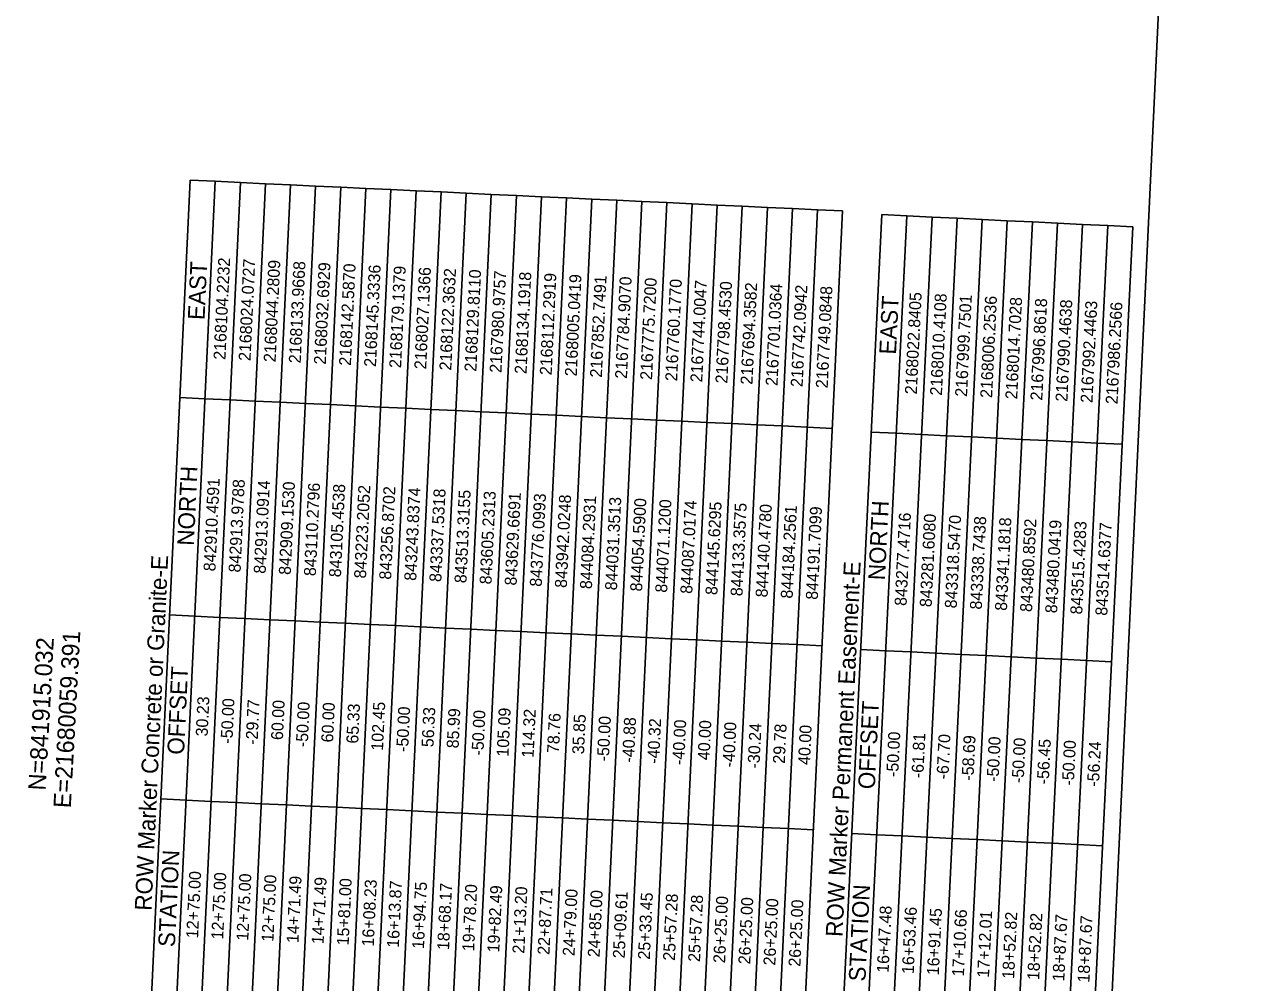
# Model space of a CAD drawing. Extents: x 2167298 to 2168977, y 841960 to 844561.
# Drawn here: x 2168145 to 2168977, y 842342 to 842987 of the extents above; entities that cross this region are included whole.
import ezdxf

# ---------------------------------------------------------------- set-up
doc = ezdxf.new("R2010")
doc.units = 0
for name, color, linetype in [('CTL GPS Vertical Text', 7, 'Continuous'), ('CTL Sheet Border CELL', 7, 'Continuous'), ('CTL Sheet Notes CELL', 7, 'Continuous'), ('CTL Sheet Table Cell', 7, 'Continuous'), ('CTL Sheet Text', 7, 'Continuous')]:
    doc.layers.add(name, color=color, linetype=linetype)

msp = doc.modelspace()

# ---------------------------------------------------------------- linework, layer by layer
at = {"layer": 'CTL Sheet Border CELL'}
msp.add_lwpolyline([(2167403.66, 844533.83), (2167297.51, 842286.33), (2168870.75, 842212.02), (2168976.9, 844459.52)], close=True, dxfattribs=at)
at = {"layer": 'CTL Sheet Table Cell'}
for p, q in [((2168226.19, 842251.66), (2168255.97, 842882.28)), ((2168255.97, 842882.28), (2168272.86, 842881.48)), ((2168243.08, 842250.86), (2168272.86, 842881.48)), ((2168259.97, 842250.06), (2168289.76, 842880.68)), ((2168272.86, 842881.48), (2168289.76, 842880.68)), ((2168276.86, 842249.27), (2168306.65, 842879.88)), ((2168289.76, 842880.68), (2168306.65, 842879.88)), ((2168293.75, 842248.47), (2168323.54, 842879.09)), ((2168306.65, 842879.88), (2168323.54, 842879.09)), ((2168310.65, 842247.67), (2168340.43, 842878.29)), ((2168323.54, 842879.09), (2168340.43, 842878.29)), ((2168327.54, 842246.87), (2168357.32, 842877.49)), ((2168340.43, 842878.29), (2168357.32, 842877.49)), ((2168344.43, 842246.08), (2168374.21, 842876.69)), ((2168357.32, 842877.49), (2168374.21, 842876.69)), ((2168361.32, 842245.28), (2168391.1, 842875.9)), ((2168374.21, 842876.69), (2168391.1, 842875.9)), ((2168378.21, 842244.48), (2168408, 842875.1)), ((2168391.1, 842875.9), (2168408, 842875.1)), ((2168395.1, 842243.68), (2168424.89, 842874.3)), ((2168408, 842875.1), (2168424.89, 842874.3)), ((2168424.89, 842874.3), (2168441.78, 842873.5)), ((2168411.99, 842242.88), (2168441.78, 842873.5)), ((2168428.89, 842242.09), (2168458.67, 842872.7)), ((2168441.78, 842873.5), (2168458.67, 842872.7)), ((2168445.78, 842241.29), (2168475.56, 842871.91)), ((2168458.67, 842872.7), (2168475.56, 842871.91)), ((2168462.67, 842240.49), (2168492.45, 842871.11)), ((2168475.56, 842871.91), (2168492.45, 842871.11)), ((2168479.56, 842239.69), (2168509.35, 842870.31)), ((2168492.45, 842871.11), (2168509.35, 842870.31)), ((2168496.45, 842238.9), (2168526.24, 842869.51)), ((2168509.35, 842870.31), (2168526.24, 842869.51)), ((2168513.34, 842238.1), (2168543.13, 842868.72)), ((2168526.24, 842869.51), (2168543.13, 842868.72)), ((2168530.24, 842237.3), (2168560.02, 842867.92)), ((2168543.13, 842868.72), (2168560.02, 842867.92)), ((2168547.13, 842236.5), (2168576.91, 842867.12)), ((2168560.02, 842867.92), (2168576.91, 842867.12)), ((2168564.02, 842235.7), (2168593.8, 842866.32)), ((2168576.91, 842867.12), (2168593.8, 842866.32)), ((2168593.8, 842866.32), (2168610.69, 842865.52)), ((2168580.91, 842234.91), (2168610.69, 842865.52)), ((2168597.8, 842234.11), (2168627.59, 842864.73)), ((2168610.69, 842865.52), (2168627.59, 842864.73)), ((2168614.69, 842233.31), (2168644.48, 842863.93)), ((2168627.59, 842864.73), (2168644.48, 842863.93)), ((2168631.58, 842232.51), (2168661.37, 842863.13)), ((2168644.48, 842863.93), (2168661.37, 842863.13)), ((2168648.48, 842231.72), (2168678.26, 842862.33)), ((2168661.37, 842863.13), (2168678.26, 842862.33)), ((2168665.37, 842230.92), (2168695.15, 842861.54)), ((2168678.26, 842862.33), (2168695.15, 842861.54)), ((2168690.79, 842228.46), (2168721.52, 842859.03)), ((2168707.68, 842227.63), (2168738.41, 842858.2)), ((2168721.52, 842859.03), (2168738.41, 842858.2)), ((2168724.57, 842226.81), (2168755.3, 842857.38)), ((2168738.41, 842858.2), (2168755.3, 842857.38)), ((2168755.3, 842857.38), (2168772.19, 842856.56)), ((2168741.46, 842225.99), (2168772.19, 842856.56)), ((2168758.35, 842225.16), (2168789.08, 842855.74)), ((2168772.19, 842856.56), (2168789.08, 842855.74)), ((2168775.24, 842224.34), (2168805.97, 842854.91)), ((2168789.08, 842855.74), (2168805.97, 842854.91)), ((2168792.13, 842223.52), (2168822.86, 842854.09)), ((2168805.97, 842854.91), (2168822.86, 842854.09)), ((2168809.02, 842222.69), (2168839.75, 842853.27)), ((2168822.86, 842854.09), (2168839.75, 842853.27)), ((2168825.91, 842221.87), (2168856.64, 842852.44)), ((2168839.75, 842853.27), (2168856.64, 842852.44)), ((2168842.8, 842221.05), (2168873.53, 842851.62)), ((2168856.64, 842852.44), (2168873.53, 842851.62)), ((2168859.69, 842220.22), (2168890.42, 842850.8)), ((2168873.53, 842851.62), (2168890.42, 842850.8)), ((2168249.06, 842735.88), (2168265.95, 842735.09)), ((2168265.95, 842735.09), (2168282.84, 842734.29)), ((2168282.84, 842734.29), (2168299.73, 842733.49)), ((2168299.73, 842733.49), (2168316.62, 842732.69)), ((2168316.62, 842732.69), (2168333.52, 842731.9)), ((2168333.52, 842731.9), (2168350.41, 842731.1)), ((2168350.41, 842731.1), (2168367.3, 842730.3)), ((2168367.3, 842730.3), (2168384.19, 842729.5)), ((2168384.19, 842729.5), (2168401.08, 842728.7)), ((2168401.08, 842728.7), (2168417.97, 842727.91)), ((2168417.97, 842727.91), (2168434.86, 842727.11)), ((2168434.86, 842727.11), (2168451.76, 842726.31)), ((2168451.76, 842726.31), (2168468.65, 842725.51)), ((2168468.65, 842725.51), (2168485.54, 842724.72)), ((2168485.54, 842724.72), (2168502.43, 842723.92)), ((2168502.43, 842723.92), (2168519.32, 842723.12)), ((2168519.32, 842723.12), (2168536.21, 842722.32)), ((2168536.21, 842722.32), (2168553.11, 842721.52)), ((2168553.11, 842721.52), (2168570, 842720.73)), ((2168570, 842720.73), (2168586.89, 842719.93)), ((2168586.89, 842719.93), (2168603.78, 842719.13)), ((2168603.78, 842719.13), (2168620.67, 842718.33)), ((2168620.67, 842718.33), (2168637.56, 842717.54)), ((2168637.56, 842717.54), (2168654.45, 842716.74)), ((2168654.45, 842716.74), (2168671.35, 842715.94)), ((2168671.35, 842715.94), (2168688.24, 842715.14)), ((2168714.39, 842712.65), (2168731.28, 842711.82)), ((2168731.28, 842711.82), (2168748.17, 842711)), ((2168748.17, 842711), (2168765.06, 842710.18)), ((2168765.06, 842710.18), (2168781.95, 842709.35)), ((2168781.95, 842709.35), (2168798.84, 842708.53)), ((2168798.84, 842708.53), (2168815.73, 842707.71)), ((2168815.73, 842707.71), (2168832.62, 842706.88)), ((2168832.62, 842706.88), (2168849.51, 842706.06)), ((2168849.51, 842706.06), (2168866.4, 842705.24)), ((2168866.4, 842705.24), (2168883.29, 842704.41)), ((2168242.14, 842589.49), (2168259.04, 842588.69)), ((2168259.04, 842588.69), (2168275.93, 842587.9)), ((2168275.93, 842587.9), (2168292.82, 842587.1)), ((2168292.82, 842587.1), (2168309.71, 842586.3)), ((2168309.71, 842586.3), (2168326.6, 842585.5)), ((2168326.6, 842585.5), (2168343.49, 842584.7)), ((2168343.49, 842584.7), (2168360.38, 842583.91)), ((2168360.38, 842583.91), (2168377.28, 842583.11)), ((2168377.28, 842583.11), (2168394.17, 842582.31)), ((2168394.17, 842582.31), (2168411.06, 842581.51)), ((2168411.06, 842581.51), (2168427.95, 842580.72)), ((2168427.95, 842580.72), (2168444.84, 842579.92)), ((2168444.84, 842579.92), (2168461.73, 842579.12)), ((2168461.73, 842579.12), (2168478.63, 842578.32)), ((2168478.63, 842578.32), (2168495.52, 842577.52)), ((2168495.52, 842577.52), (2168512.41, 842576.73)), ((2168512.41, 842576.73), (2168529.3, 842575.93)), ((2168529.3, 842575.93), (2168546.19, 842575.13)), ((2168546.19, 842575.13), (2168563.08, 842574.33)), ((2168563.08, 842574.33), (2168579.97, 842573.54)), ((2168579.97, 842573.54), (2168596.87, 842572.74)), ((2168596.87, 842572.74), (2168613.76, 842571.94)), ((2168613.76, 842571.94), (2168630.65, 842571.14)), ((2168630.65, 842571.14), (2168647.54, 842570.34)), ((2168647.54, 842570.34), (2168664.43, 842569.55)), ((2168664.43, 842569.55), (2168681.32, 842568.75)), ((2168707.25, 842566.26), (2168724.14, 842565.44)), ((2168724.14, 842565.44), (2168741.03, 842564.62)), ((2168741.03, 842564.62), (2168757.92, 842563.79)), ((2168757.92, 842563.79), (2168774.81, 842562.97)), ((2168774.81, 842562.97), (2168791.7, 842562.15)), ((2168791.7, 842562.15), (2168808.59, 842561.32)), ((2168808.59, 842561.32), (2168825.48, 842560.5)), ((2168825.48, 842560.5), (2168842.37, 842559.68)), ((2168842.37, 842559.68), (2168859.26, 842558.85)), ((2168859.26, 842558.85), (2168876.15, 842558.03)), ((2168236.29, 842465.62), (2168253.18, 842464.82)), ((2168253.18, 842464.82), (2168270.08, 842464.02)), ((2168270.08, 842464.02), (2168286.97, 842463.23)), ((2168286.97, 842463.23), (2168303.86, 842462.43)), ((2168303.86, 842462.43), (2168320.75, 842461.63)), ((2168320.75, 842461.63), (2168337.64, 842460.83)), ((2168337.64, 842460.83), (2168354.53, 842460.04)), ((2168354.53, 842460.04), (2168371.43, 842459.24)), ((2168371.43, 842459.24), (2168388.32, 842458.44)), ((2168388.32, 842458.44), (2168405.21, 842457.64)), ((2168405.21, 842457.64), (2168422.1, 842456.84)), ((2168422.1, 842456.84), (2168438.99, 842456.05)), ((2168438.99, 842456.05), (2168455.88, 842455.25)), ((2168455.88, 842455.25), (2168472.77, 842454.45)), ((2168472.77, 842454.45), (2168489.67, 842453.65)), ((2168489.67, 842453.65), (2168506.56, 842452.86)), ((2168506.56, 842452.86), (2168523.45, 842452.06)), ((2168523.45, 842452.06), (2168540.34, 842451.26)), ((2168540.34, 842451.26), (2168557.23, 842450.46)), ((2168557.23, 842450.46), (2168574.12, 842449.66)), ((2168574.12, 842449.66), (2168591.02, 842448.87)), ((2168591.02, 842448.87), (2168607.91, 842448.07)), ((2168607.91, 842448.07), (2168624.8, 842447.27)), ((2168624.8, 842447.27), (2168641.69, 842446.47)), ((2168641.69, 842446.47), (2168658.58, 842445.68)), ((2168658.58, 842445.68), (2168675.47, 842444.88)), ((2168701.21, 842442.4), (2168718.1, 842441.58)), ((2168718.1, 842441.58), (2168735, 842440.75)), ((2168735, 842440.75), (2168751.89, 842439.93)), ((2168751.89, 842439.93), (2168768.78, 842439.11)), ((2168768.78, 842439.11), (2168785.67, 842438.28)), ((2168785.67, 842438.28), (2168802.56, 842437.46)), ((2168802.56, 842437.46), (2168819.45, 842436.64)), ((2168819.45, 842436.64), (2168836.34, 842435.81)), ((2168836.34, 842435.81), (2168853.23, 842434.99)), ((2168853.23, 842434.99), (2168870.12, 842434.17))]:
    msp.add_line(p, q, dxfattribs=at)

# ---------------------------------------------------------------- texts
at = {"layer": 'CTL GPS Vertical Text'}
for s, p in [('E=21680059.391', (2168175.58, 842459.25)), ('N=841915.032', (2168158.67, 842471.14))]:
    msp.add_text(s, height=11.6923, rotation=86.87788, dxfattribs=at).set_placement(p)
at = {"layer": 'CTL Sheet Notes CELL'}
for s, height, rotation, p in [('EAST', 11.274, 87.29593, (2168265.62, 842787.93)), ('EAST', 11.274, 87.20981, (2168731.03, 842764.67)), ('NORTH', 11.274, 87.29593, (2168258.45, 842635.95)), ('NORTH', 11.274, 87.20981, (2168723.62, 842612.7)), ('ROW Marker Concrete or Granite-E', 11.2736, 87.29593, (2168229.91, 842390.21)), ('ROW Marker Permanent Easement-E', 11.2736, 87.20981, (2168694.99, 842372.58)), ('OFFSET', 11.274, 87.29593, (2168251.8, 842495.24)), ('OFFSET', 11.274, 87.20981, (2168716.77, 842471.99)), ('STATION', 11.274, 87.29593, (2168245.69, 842365.78)), ('STATION', 11.274, 87.20981, (2168710.46, 842342.54))]:
    msp.add_text(s, height=height, rotation=rotation, dxfattribs=at).set_placement(p)
at = {"layer": 'CTL Sheet Text'}
for s, height, rotation, p in [('2168104.2232', 8.0526, 87.29593, (2168279.68, 842761.14)), ('2168024.0727', 8.0526, 87.29593, (2168296.57, 842760.35)), ('2168044.2809', 8.0526, 87.29593, (2168313.46, 842759.55)), ('2168133.9668', 8.0526, 87.29593, (2168330.35, 842758.75)), ('2168032.6929', 8.0526, 87.29593, (2168347.24, 842757.95)), ('2168142.5870', 8.0526, 87.29593, (2168364.13, 842757.15)), ('2168145.3336', 8.0526, 87.29593, (2168381.02, 842756.36)), ('2168179.1379', 8.0526, 87.29593, (2168397.92, 842755.56)), ('2168027.1366', 8.0526, 87.29593, (2168414.81, 842754.76)), ('2168122.3632', 8.0526, 87.29593, (2168431.7, 842753.96)), ('2168129.8110', 8.0526, 87.29593, (2168448.59, 842753.16)), ('2167980.9757', 8.0526, 87.29593, (2168465.48, 842752.37)), ('2168134.1918', 8.0526, 87.29593, (2168482.37, 842751.57)), ('2168112.2919', 8.0526, 87.29593, (2168499.27, 842750.77)), ('2168005.0419', 8.0526, 87.29593, (2168516.16, 842749.97)), ('2167852.7491', 8.0526, 87.29593, (2168533.05, 842749.18)), ('2167784.9070', 8.0526, 87.29593, (2168549.94, 842748.38)), ('2167775.7200', 8.0526, 87.29593, (2168566.83, 842747.58)), ('2167760.1770', 8.0526, 87.29593, (2168583.72, 842746.78)), ('2167744.0047', 8.0526, 87.29593, (2168600.61, 842745.98)), ('2167798.4530', 8.0526, 87.29593, (2168617.51, 842745.19)), ('2167694.3582', 8.0526, 87.29593, (2168634.4, 842744.39)), ('2167701.0364', 8.0526, 87.29593, (2168651.29, 842743.59)), ('2167742.0942', 8.0526, 87.29593, (2168668.18, 842742.79)), ('2167749.0848', 8.0526, 87.29593, (2168685.07, 842742)), ('2168022.8405', 8.0526, 87.20981, (2168745.04, 842737.86)), ('2168010.4108', 8.0526, 87.20981, (2168761.93, 842737.03)), ('2167999.7501', 8.0526, 87.20981, (2168778.82, 842736.21)), ('2168006.2536', 8.0526, 87.20981, (2168795.71, 842735.39)), ('2168014.7028', 8.0526, 87.20981, (2168812.6, 842734.57)), ('2167996.8618', 8.0526, 87.20981, (2168829.49, 842733.74)), ('2167990.4638', 8.0526, 87.20981, (2168846.38, 842732.92)), ('2167992.4463', 8.0526, 87.20981, (2168863.27, 842732.1)), ('2167986.2566', 8.0526, 87.20981, (2168880.16, 842731.27)), ('842910.4591', 8.0526, 87.29593, (2168272.95, 842618.74)), ('842913.9788', 8.0526, 87.29593, (2168289.84, 842617.94)), ('842913.0914', 8.0526, 87.29593, (2168306.73, 842617.14)), ('842909.1530', 8.0526, 87.29593, (2168323.62, 842616.35)), ('843110.2796', 8.0526, 87.29593, (2168340.52, 842615.55)), ('843105.4538', 8.0526, 87.29593, (2168357.41, 842614.75)), ('843223.2052', 8.0526, 87.29593, (2168374.3, 842613.95)), ('843256.8702', 8.0526, 87.29593, (2168391.19, 842613.16)), ('843243.8374', 8.0526, 87.29593, (2168408.08, 842612.36)), ('843337.5318', 8.0526, 87.29593, (2168424.97, 842611.56)), ('843513.3155', 8.0526, 87.29593, (2168441.87, 842610.76)), ('843605.2313', 8.0526, 87.29593, (2168458.76, 842609.96)), ('843629.6691', 8.0526, 87.29593, (2168475.65, 842609.17)), ('843776.0993', 8.0526, 87.29593, (2168492.54, 842608.37)), ('843942.0248', 8.0526, 87.29593, (2168509.43, 842607.57)), ('844084.2931', 8.0526, 87.29593, (2168526.32, 842606.77)), ('844031.3513', 8.0526, 87.29593, (2168543.21, 842605.98)), ('844054.5900', 8.0526, 87.29593, (2168560.11, 842605.18)), ('844071.1200', 8.0526, 87.29593, (2168577, 842604.38)), ('844087.0174', 8.0526, 87.29593, (2168593.89, 842603.58)), ('844145.6295', 8.0526, 87.29593, (2168610.78, 842602.78)), ('844133.3575', 8.0526, 87.29593, (2168627.67, 842601.99)), ('844140.4780', 8.0526, 87.29593, (2168644.56, 842601.19)), ('844184.2561', 8.0526, 87.29593, (2168661.45, 842600.39)), ('844191.7099', 8.0526, 87.29593, (2168678.35, 842599.59)), ('843277.4716', 8.0526, 87.20981, (2168738.1, 842595.46)), ('843281.6080', 8.0526, 87.20981, (2168754.99, 842594.64)), ('843318.5470', 8.0526, 87.20981, (2168771.88, 842593.82)), ('843338.7438', 8.0526, 87.20981, (2168788.77, 842593)), ('843341.1818', 8.0526, 87.20981, (2168805.66, 842592.17)), ('843480.8592', 8.0526, 87.20981, (2168822.55, 842591.35)), ('843480.0419', 8.0526, 87.20981, (2168839.44, 842590.53)), ('843515.4283', 8.0526, 87.20981, (2168856.33, 842589.7)), ('843514.6377', 8.0526, 87.20981, (2168873.22, 842588.88)), ('30.23', 8.053, 87.29593, (2168267.7, 842507.55)), ('-50.00', 8.053, 87.29593, (2168284.4, 842502.76)), ('-29.77', 8.053, 87.29593, (2168301.29, 842501.96)), ('60.00', 8.053, 87.29593, (2168318.37, 842505.15)), ('-50.00', 8.053, 87.29593, (2168335.08, 842500.37)), ('60.00', 8.053, 87.29593, (2168352.16, 842503.56)), ('65.33', 8.053, 87.29593, (2168369.05, 842502.76)), ('102.45', 8.053, 87.29593, (2168385.75, 842497.97)), ('-50.00', 8.053, 87.29593, (2168402.64, 842497.18)), ('56.33', 8.053, 87.29593, (2168419.72, 842500.37)), ('85.99', 8.053, 87.29593, (2168436.61, 842499.57)), ('-50.00', 8.053, 87.29593, (2168453.32, 842494.78)), ('105.09', 8.053, 87.29593, (2168470.21, 842493.98)), ('114.32', 8.053, 87.29593, (2168487.1, 842493.19)), ('78.76', 8.053, 87.29593, (2168504.18, 842496.38)), ('35.85', 8.053, 87.29593, (2168521.07, 842495.58)), ('-50.00', 8.053, 87.29593, (2168537.77, 842490.79)), ('-40.88', 8.053, 87.29593, (2168554.67, 842490)), ('-40.32', 8.053, 87.29593, (2168571.56, 842489.2)), ('-40.00', 8.053, 87.29593, (2168588.45, 842488.4)), ('40.00', 8.053, 87.29593, (2168605.53, 842491.59)), ('-40.00', 8.053, 87.29593, (2168622.23, 842486.8)), ('-30.24', 8.053, 87.29593, (2168639.12, 842486.01)), ('29.78', 8.053, 87.29593, (2168656.2, 842489.2)), ('40.00', 8.053, 87.29593, (2168673.09, 842488.4)), ('-50.00', 8.053, 87.20981, (2168732.49, 842480.29)), ('-61.81', 8.053, 87.20981, (2168749.38, 842479.47)), ('-67.70', 8.053, 87.20981, (2168766.27, 842478.65)), ('-58.69', 8.053, 87.20981, (2168783.16, 842477.82)), ('-50.00', 8.053, 87.20981, (2168800.05, 842477)), ('-50.00', 8.053, 87.20981, (2168816.94, 842476.18)), ('-56.45', 8.053, 87.20981, (2168833.83, 842475.35)), ('-50.00', 8.053, 87.20981, (2168850.72, 842474.53)), ('-56.24', 8.053, 87.20981, (2168867.61, 842473.71)), ('12+75.00', 8.053, 87.29593, (2168261.28, 842371.71)), ('12+75.00', 8.053, 87.29593, (2168278.17, 842370.91)), ('12+75.00', 8.053, 87.29593, (2168295.07, 842370.11)), ('12+75.00', 8.053, 87.29593, (2168311.96, 842369.31)), ('14+71.49', 8.053, 87.29593, (2168328.85, 842368.52)), ('14+71.49', 8.053, 87.29593, (2168345.74, 842367.72)), ('15+81.00', 8.053, 87.29593, (2168362.63, 842366.92)), ('16+08.23', 8.053, 87.29593, (2168379.52, 842366.12)), ('16+13.87', 8.053, 87.29593, (2168396.41, 842365.32)), ('16+94.75', 8.053, 87.29593, (2168413.31, 842364.53)), ('18+68.17', 8.053, 87.29593, (2168430.2, 842363.73)), ('19+78.20', 8.053, 87.29593, (2168447.09, 842362.93)), ('19+82.49', 8.053, 87.29593, (2168463.98, 842362.13)), ('21+13.20', 8.053, 87.29593, (2168480.87, 842361.34)), ('22+87.71', 8.053, 87.29593, (2168497.76, 842360.54)), ('24+79.00', 8.053, 87.29593, (2168514.66, 842359.74)), ('24+85.00', 8.053, 87.29593, (2168531.55, 842358.94)), ('25+09.61', 8.053, 87.29593, (2168548.44, 842358.14)), ('25+33.45', 8.053, 87.29593, (2168565.33, 842357.35)), ('25+57.28', 8.053, 87.29593, (2168582.22, 842356.55)), ('25+57.28', 8.053, 87.29593, (2168599.11, 842355.75)), ('26+25.00', 8.053, 87.29593, (2168616, 842354.95)), ('26+25.00', 8.053, 87.29593, (2168632.9, 842354.16)), ('26+25.00', 8.053, 87.29593, (2168649.79, 842353.36)), ('26+25.00', 8.053, 87.29593, (2168666.68, 842352.56)), ('16+47.48', 8.053, 87.20981, (2168726.06, 842348.45)), ('16+53.46', 8.053, 87.20981, (2168742.95, 842347.63)), ('16+91.45', 8.053, 87.20981, (2168759.84, 842346.8)), ('17+10.66', 8.053, 87.20981, (2168776.73, 842345.98)), ('17+12.01', 8.053, 87.20981, (2168793.62, 842345.16)), ('18+52.82', 8.053, 87.20981, (2168810.51, 842344.33)), ('18+52.82', 8.053, 87.20981, (2168827.4, 842343.51)), ('18+87.67', 8.053, 87.20981, (2168844.29, 842342.69)), ('18+87.67', 8.053, 87.20981, (2168861.18, 842341.86))]:
    msp.add_text(s, height=height, rotation=rotation, dxfattribs=at).set_placement(p)

doc.saveas('drawing.dxf')
